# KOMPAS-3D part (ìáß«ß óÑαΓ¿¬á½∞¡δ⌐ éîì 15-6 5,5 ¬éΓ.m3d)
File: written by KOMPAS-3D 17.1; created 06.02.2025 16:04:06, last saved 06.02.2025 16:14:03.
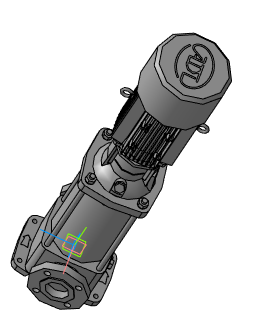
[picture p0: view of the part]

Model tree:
1. Операция без истории:1  (labels: Насос вертикальный ВМН 15-6 5,5 кВт)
